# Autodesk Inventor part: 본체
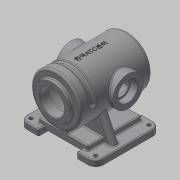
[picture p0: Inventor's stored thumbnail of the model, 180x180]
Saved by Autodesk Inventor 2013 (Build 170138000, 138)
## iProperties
Created: 2015-10
Part Number: 본체
Document SubType Name: Modeling
Designer: mdu
Density: 1 g/cm^3
Material: 일반
Mass: 1694.51 g
Surface Area: 2715.66 cm^2
Volume: 1694.51 cm^3
Author: mdu
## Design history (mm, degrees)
sketch "스케치1"
  geometry: L1 (-100, 85)-(-50, 85); L2 (-50, 85)-(-50, -85); L3 (-50, -85)-(-100, -85); L4 (-100, -85)-(-100, 85); L5 (50, 85)-(100, 85); L6 (100, 85)-(100, -85); L7 (100, -85)-(50, -85); L8 (50, -85)-(50, 85); 3 further points
  constraints: 16 end point, 4 parallel, 2 equal length, 2 horizontal, 2 horizontal alignment, 2 midpoint, 2 perpendicular
  dimensions: "d0" = 100 distance between parallel lines of L8 L2; "d1" = 170 distance of L3.end L1.start; "d3" = 200 distance between parallel lines of L6 L4; "d4" = 50 distance from line of point (0, 0) L2 (= 0.5 x d0)
extrude "돌출1" new body sketch "스케치1" distance "d5" = 16; taper "d6" = 0 deg
node "작업 평면1"
sketch "스케치2"
  geometry: L1 (-65, 70)-(65, 70); L2 (65, 70)-(65, -70); L3 (65, -70)-(-65, -70); L4 (-65, -70)-(-65, 70); 3 further points
  constraints: 8 end point, 2 midpoint, 2 parallel, 1 horizontal, 1 horizontal alignment, 1 perpendicular, 1 vertical alignment
  dimensions: "d8" = 130 distance of L2.end L3.end; "d9" = 140 distance of L1.end L2.end
extrude "돌출2" join sketch "스케치2" distance "d10" = 20; taper "d11" = 0 deg
sketch "스케치3"
  geometry: L1 (-100, 110)-(100, 110); L2 (85, 0)-(-85, 0) reference; L3 (100, 110)-(100, 175); L4 (100, 175)-(-90, 175); L5 (-90, 175)-(-90, 156); L6 (-90, 156)-(-100, 156); L7 (-100, 156)-(-100, 110); L8 (90, 110)-(90, 165); L9 (90, 165)-(-75, 165); L10 (-75, 165)-(-75, 110); L11 (-100, 142.5)-(-75, 142.5); 3 further points
  constraints: 20 end point, 5 perpendicular, 4 parallel, 4 point on line, 2 midpoint, 1 horizontal, 1 vertical alignment
  dimensions: "d12" = 110 distance from line of L2 L1.end; "d13" = 200 distance of L1.start L1.end; "d14" = 130 diameter of L4 L1; "d15" = 92 diameter of L6 L1; "d16" = 10 distance of L5.end L6.end; "d42" = 110 diameter of L9 L1; "d43" = 10 distance between parallel lines of L3 L8; "d44" = 25 distance between parallel lines of L10 L7; "d45" = 65 diameter of L11 L1
revolve "회전1" sketch "스케치3" stored, may be unused: angle "d17" = 90 deg
sketch "스케치4"
  geometry: L1 (-50, 70)-(50, 70) reference; L2 (50, -70)-(-50, -70) reference; L3 (-10, 70)-(-10, -70); L4 (10, -70)-(10, 70); 1 further point
  constraints: 4 end point, 4 point on line, 2 perpendicular
  dimensions: "d18" = 20 distance between parallel lines of L4 L3; "d19" = 10 distance from line of point (0, 0) L3
extrude "돌출3" join sketch "스케치4" stored distance "d20" = 10; taper "d21" = 0 deg
node "작업 평면2"
sketch "스케치5"
  geometry: L1 (-50, -8)-(0, -8) reference; L2 (100, -8)-(150, -8) reference; L3 (-40, -8)-(-8.943, -74.601); L4 (140, -8)-(108.943, -74.601); L5 (-50, 8)-(-50, -8) reference; L6 (150, 8)-(150, -8) reference; A1 r 65 centre (50, -102) between (-8.943, -74.601) and (108.943, -74.601) reference; 1 further point
  constraints: 4 end point, 2 point on circle, 2 point on line, 1 equal length
  dimensions: "d23" = 10 distance from line of L3.start L5; "d24" = 10 distance from line of L4.start L6; "d25" = 25 deg angle of L3 L5
feature "리브1" sketch "스케치5" dims "d26" = 1, "d27" = 20, "d28" = 0
node "작업 평면3"
sketch "스케치6"
  geometry: L1 (100, 156)-(100, 64) reference; C1 r 40 at (-25, 110); 2 further points
  constraints: 1 centre point, 1 horizontal alignment, 1 midpoint
  dimensions: "d37" = 80 diameter of C1; "d38" = 125 distance from line of C1.centre L1
extrude "돌출4" join sketch "스케치6" stored distance "d39" = 10; taper "d40" = 0 deg
hole "구멍1" diameter "d48" = 42; stored, may be unused: countersink angle "d52" = 90 deg, drill point angle "d54" = 118 deg; dims "d46" = 10, "d47" = 10, "d49" = 6, "d50" = 52, "d51" = 18, "d53" = 8
sketch "스케치7"
  geometry: C1 r 40 at (0, 0) reference; 2 further points
  constraints: 1 horizontal alignment
  dimensions: "d55" = 32.5 distance of point (32.5, 0) C1.centre
hole "구멍2" sketch "스케치7" at (32.5, 0) diameter "d56" = 3.242; stored, may be unused: countersink angle "d60" = 90 deg, drill point angle "d62" = 118 deg; dims "d57" = 11, "d58" = 52, "d59" = 18, "d61" = 13
sketch "스케치8"
  geometry: C1 r 46 at (0, 0) reference; 2 further points
  constraints: 1 vertical alignment
  dimensions: "d66" = 39 distance of C1.centre point (0, 39)
hole "구멍3" sketch "스케치8" at (0, 39) diameter "d67" = 3.242; stored, may be unused: countersink angle "d71" = 90 deg, drill point angle "d73" = 118 deg; dims "d68" = 11, "d69" = 52, "d70" = 18, "d72" = 13
fillet "모깎기7" dims "d77" = 20, "d78" = 5, "d79" = 3, "d80" = 10, "d107" = 10
fillet "모깎기8" dims "d81" = 3
fillet "모깎기9" dims "d82" = 3
fillet "모깎기10" dims "d83" = 3, "d84" = 0.3
chamfer "모따기1" distance "d85" = 1; stored, may be unused: second distance "d86" = 2, angle "d87" = 45 deg
node "작업 평면4"
sketch "스케치10"
  geometry: 5 further points
  constraints: 2 horizontal alignment, 2 vertical alignment
  dimensions: "d90" = 170 distance of point (85, 70) point (-85, 70); "d91" = 140 distance of point (-85, 70) point (-85, -70); "d92" = 70 vertical distance of point (0, 0) point (-85, -70) (= 0.5 x d91); "d93" = 85 horizontal distance of point (0, 0) point (-85, 70) (= 0.5 x d90)
hole "구멍4" sketch "스케치10" at (-85, 70), (85, 70), (85, -70), (-85, -70) diameter "d94" = 10; stored, may be unused: countersink angle "d98" = 90 deg, drill point angle "d100" = 118 deg; dims "d95" = 6, "d96" = 4, "d97" = 2, "d99" = 8
node "작업 평면5"
sketch "스케치12" dims "d22" = -90
  geometry: L1 (-65, -90)-(65, -90) reference; L2 (65, 85)-(-65, 85) reference; L3 (0, -90)-(0, 85); 3 further points
  constraints: 3 midpoint, 2 end point, 1 coincident, 1 other
feature "엠보싱3" sketch "스케치12" dims "d105" = 1, "d106" = 0
node "작업축1"
sketch "스케치13"
  geometry: L1 (-85, 175)-(90, 175) reference; L2 (-65, 175)-(-50, 175); L3 (-50, 175)-(-50, 170); L4 (-50, 170)-(-65, 170); L5 (-65, 170)-(-65, 175); L6 (-90, 50)-(-90, 170) reference; L7 (-140, 110)-(140, 110) reference; 1 further point
  constraints: 8 end point, 2 parallel, 1 horizontal, 1 perpendicular, 1 point on line
  dimensions: "d108" = 25 distance between parallel lines of L5 L6; "d109" = 15 distance of L3.end L4.end; "d110" = 5 distance of L2.end L3.end
revolve "회전2" sketch "스케치13" stored, may be unused: angle "d111" = 180 deg
fillet "모깎기11" dims "d112" = 5
fillet "모깎기12" dims "d113" = 5
fillet "모깎기13" dims "d114" = 3
node "솔리드1"
mirror "대칭1"
pattern_circular "원형 패턴1" dims angle "d64" = 360 deg
mirror "대칭3"
pattern_circular "원형 패턴2" dims angle "d75" = 360 deg
other parameters: "d7" = 8, "d36" = -75
